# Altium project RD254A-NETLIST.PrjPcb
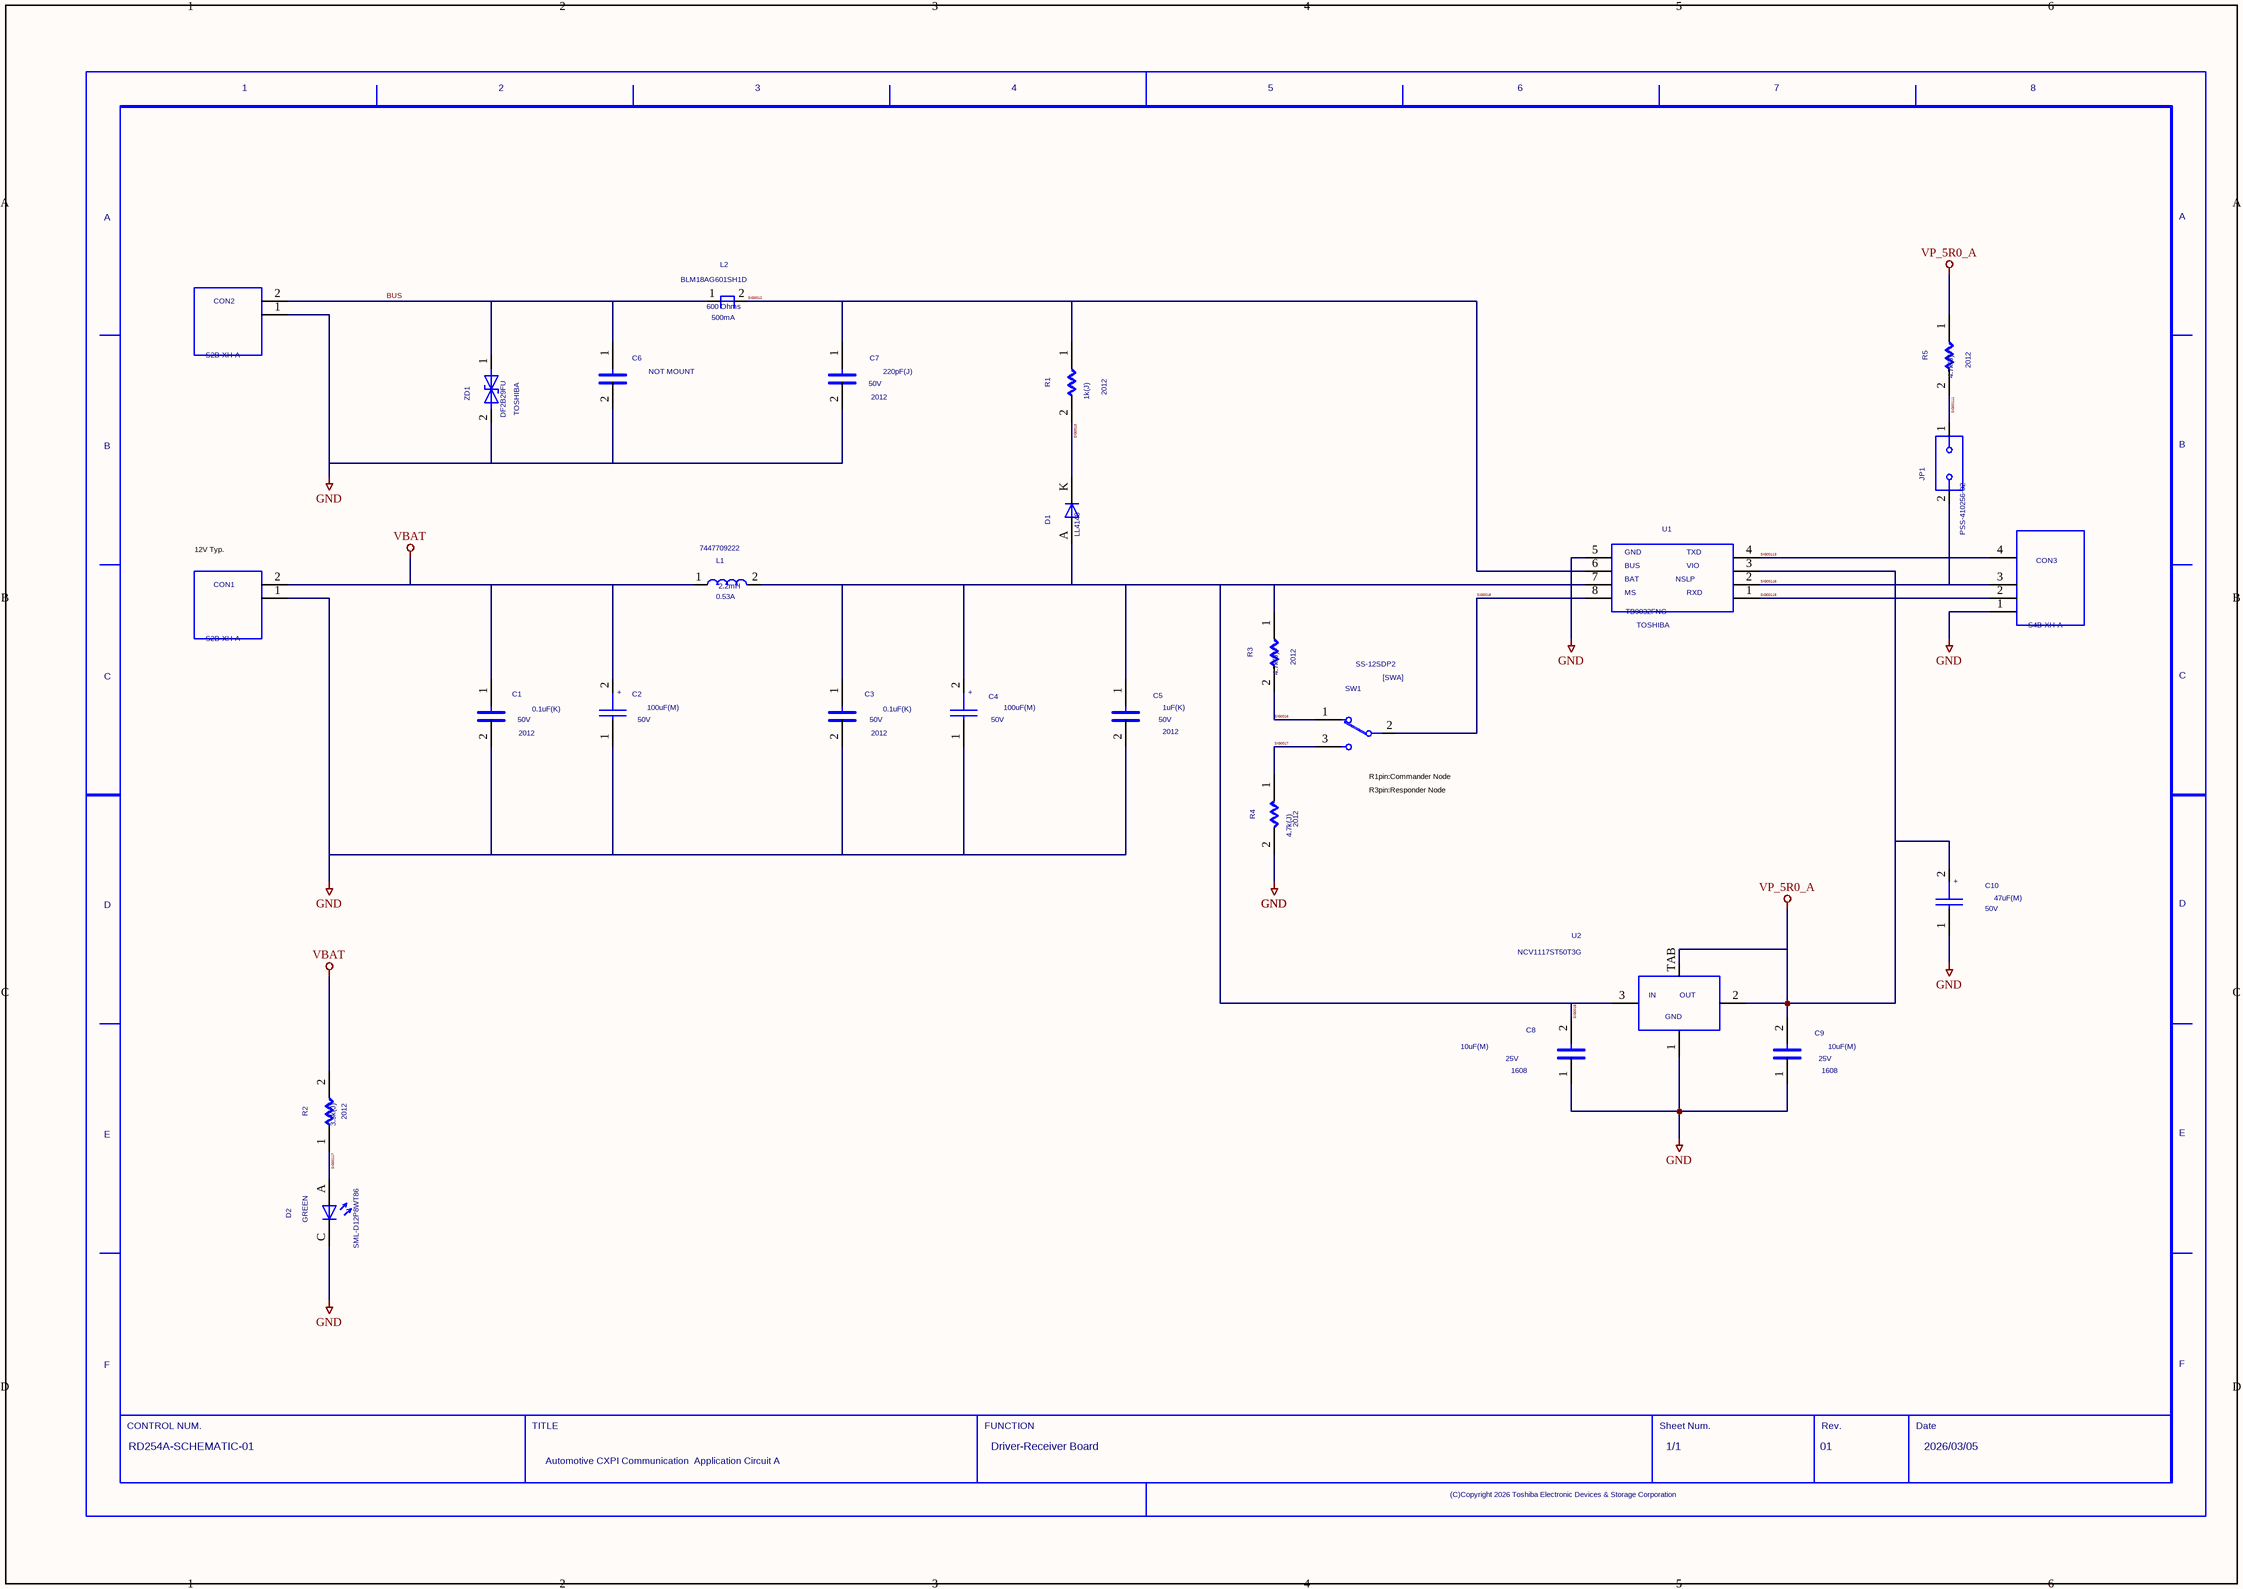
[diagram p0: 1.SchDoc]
1 sheet, 28 parts. Net scope: global (net labels, ports and power ports of the same name join across sheets).

## Sheet 1.SchDoc
size 420 x 297 mm

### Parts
C1  VAL1: 0.1uF(K)  VAL2: 50V  SIZECODESMD: 2012  (hidden comment: C)
C2  VAL1: 100uF(M)  VAL2: 50V  (hidden comment: CP)
C3  VAL1: 0.1uF(K)  VAL2: 50V  SIZECODESMD: 2012  (hidden comment: C)
C4  VAL1: 100uF(M)  VAL2: 50V  (hidden comment: CP)
C5  VAL1: 1uF(K)  VAL2: 50V  SIZECODESMD: 2012  (hidden comment: C)
C6  NOTMOUNT: NOT MOUNT  (hidden comment: C)
C7  VAL1: 220pF(J)  VAL2: 50V  SIZECODESMD: 2012  (hidden comment: C)
C8  VAL1: 10uF(M)  VAL2: 25V  SIZECODESMD: 1608  (hidden comment: C)
C9  VAL1: 10uF(M)  VAL2: 25V  SIZECODESMD: 1608  (hidden comment: C)
C10  VAL1: 47uF(M)  VAL2: 50V  (hidden comment: CP)
CON1  S2B-XH-A
CON2  S2B-XH-A
CON3  S4B-XH-A
D1  VAL3: LL4148  (hidden comment: D)
D2  VAL2: GREEN  VAL3: SML-D12P8WT86  (hidden comment: LED)
JP1  PSS-410256-02
L1  VAL1: 2.2mH  VAL2: 0.53A  VAL3: 7447709222  (hidden comment: L)
L2  VAL2: 500mA  VAL3: BLM18AG601SH1D  VAL1: 600 Ohms  (hidden comment: FB)
R1  VAL1: 1k(J)  SIZECODESMD: 2012  (hidden comment: R)
R2  VAL1: 3.3k(J)  SIZECODESMD: 2012  (hidden comment: R)
R3  VAL1: 4.7k(J)  SIZECODESMD: 2012  (hidden comment: R)
R4  VAL1: 4.7k(J)  SIZECODESMD: 2012  (hidden comment: R)
R5  VAL1: 4.7k(J)  SIZECODESMD: 2012  (hidden comment: R)
SW1  VAL3: SS-12SDP2  (hidden comment: SWA)
U1  USERCOMPTEXT3: TOSHIBA  (hidden comment: TB9032FNG)
U2  VAL3: NCV1117ST50T3G  (hidden comment: LD1117S50TR)
U?  DATE: 2026/03/05  DRAWINGNUMBER: RD254A-SCHEMATIC-01  TITLE: Automotive CXPI Communication / Application Circuit A  FUNCTION: Driver-Receiver Board  SHEETNUMBER: 1/1  REVISION: 01  (hidden comment: WAKU_DEF100)
ZD1  USERCOMPTEXT3: TOSHIBA  VAL3: DF2B29FU  (hidden comment: ZDB)

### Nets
GND: C1.2 C2.1 C3.2 C4.1 C5.2 C6.2 C7.2 C8.1 C9.1 C10.1 CON1.1 CON2.1 CON3.1 D2.C R4.2 U1.5 U2.1 ZD1.2
VBAT: C1.1 C2.2 CON1.2 L1.1 R2.2
VP_5R0_A: C9.2 C10.2 R5.1 U1.3 U2.2 U2.TAB
BUS: C6.1 CON2.2 L2.1 ZD1.1
SIG0012: C7.1 L2.2 R1.1 U1.6
SIG0013: D1.K(C) R1.2
SIG0015: C3.1 C4.2 C5.1 C8.2 D1.A L1.2 R3.1 U1.7 U2.3
SIG0016: R3.2 SW1.1
SIG0017: R4.1 SW1.3
SIG0018: SW1.2 U1.8
SIG00111: JP1.1 R5.2
SIG00113: CON3.4 U1.4
SIG00115: CON3.2 U1.1
SIG00116: CON3.3 JP1.2 U1.2
SIG00117: D2.A R2.1

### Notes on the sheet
- (near CON1) 12V Typ.
  6V to 18V
- (near SW1) R1pin:Commander Node
- (near SW1) R3pin:Responder Node

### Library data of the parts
C1 C3 C5-C7 = C: OriginalSymbolOrigin: (2540,7620); SAVECOUNT: 0
C2 C4 C10 = CP: SAVEAREA0: -1450,-153,20294,13055; SAVECOUNT: 52; TIME: 15:02:55; UPDATEUSER: fukuda-y; UPDATETIME: 16:13:42; OriginalSymbolOrigin: (2540,10160); COMP: C
C8 C9 = C#1: OriginalSymbolOrigin: (2540,7620); CaptureCellPackProp: C##1; SAVECOUNT: 0
CON1 CON2 = S2B-XH-A: SAVEAREA0: -63393,-16950,474261,314592; TIME: 14:30:25; UPDATEUSER: t5459927; UPDATETIME: 10:47:53; SAVECOUNT: 18; OriginalSymbolOrigin: (0,12700)
CON3 = S4B-XH-A: SAVEAREA0: -63393,-16950,474261,314592; TIME: 14:30:25; UPDATEUSER: t5459927; UPDATETIME: 17:06:20; SAVECOUNT: 19; OriginalSymbolOrigin: (0,12700)
D1 = D: SAVEAREA0: -225,-91,12804,7836; SAVECOUNT: 3; TIME: 14:49:55; UPDATEUSER: 19870035; UPDATETIME: 14:20:16; OriginalSymbolOrigin: (5080,5080)
D2 = LED: SAVEAREA0: -6799,-183,19247,15664; TIME: 14:49:55; UPDATEUSER: fukuda-y; UPDATETIME: 13:54:07; SAVECOUNT: 4; OriginalSymbolOrigin: (5080,7620)
JP1 = PSS-410256-02: SAVEAREA0: -63393,-16950,474261,314592; TIME: 14:30:25; UPDATEUSER: t5459927; UPDATETIME: 18:56:33; SAVECOUNT: 22; OriginalSymbolOrigin: (2540,5080)
L1 = L: OriginalSymbolOrigin: (2540,5080); COMP: BLM18AG601SH1D; SAVECOUNT: 0
L2 = FB: SAVEAREA0: -63393,-16950,474261,314592; TIME: 14:30:25; UPDATEUSER: t5459927; UPDATETIME: 11:02:03; SAVECOUNT: 20; OriginalSymbolOrigin: (7620,7620); SIZECODESMD: 1608
R1 R3 R5 = R: VAL2: 250mW; OriginalSymbolOrigin: (5080,5080); SAVECOUNT: 0
R2 R4 = R#1: VAL2: 250mW; OriginalSymbolOrigin: (5080,5080); CaptureCellPackProp: R##1; SAVECOUNT: 0
SW1 = SWA: OriginalSymbolOrigin: (2540,10160); SAVECOUNT: 0
U1 = TB9032FNG: SAVEAREA0: -63393,-16950,474261,314592; TIME: 14:30:25; UPDATEUSER: t5459927; UPDATETIME: 14:36:30; SAVECOUNT: 16; OriginalSymbolOrigin: (5080,12700)
U2 = LD1117S50TR: SAVEAREA0: -63393,-16950,474261,314592; TIME: 14:30:25; UPDATEUSER: t5459927; UPDATETIME: 09:55:03; SAVECOUNT: 16; OriginalSymbolOrigin: (5080,15240); COMP: NCV1117DT50RKG
U? = WAKU_DEF100: PLOTTIME: HH:MM; SAVEAREA0: -63393,-16950,474261,314592; TIME: 14:30:25; UPDATEUSER: t5459927; UPDATETIME: 17:08:01; SAVECOUNT: 5; OriginalSymbolOrigin: (10160,284480); SHTSAVECOUNT: 36
ZD1 = ZDB: SAVEAREA0: -4630,-153,17114,13055; TIME: 14:49:55; UPDATEUSER: fukuda-y; UPDATETIME: 08:22:19; SAVECOUNT: 6; OriginalSymbolOrigin: (2540,5080)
